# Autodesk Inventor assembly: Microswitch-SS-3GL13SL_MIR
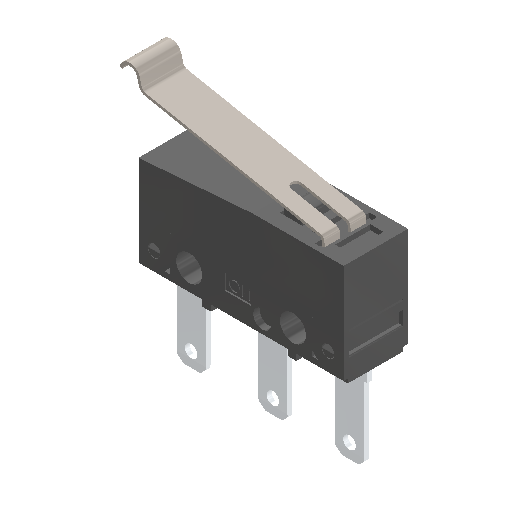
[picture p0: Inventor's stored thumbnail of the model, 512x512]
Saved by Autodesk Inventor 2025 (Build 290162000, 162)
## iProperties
Created: 2018-02
Part Number: Microswitch-SS-3GL13SL_MIR
Description: STEP AP214
Document SubType Name: Assembly
Designer: Ryzen5700u
Title: Microswitch-SS-3GL13SL.STEP
Revision Number: ANY
Sending System: SolidWorks 2018
Preprocessor: SwSTEP 2.0
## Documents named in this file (5)
- C:\Users\Ryzen5700u\Desktop\slider_2040\Microswitch-SS-3GL13SL\Microswitch-SS-3GL13SL_MIR.iam
- C:\Users\Ryzen5700u\Desktop\slider_2040\Microswitch-SS-3GL13SL\limit-switch-bottomcase_MIR.ipt
- C:\Users\Ryzen5700u\Desktop\slider_2040\Microswitch-SS-3GL13SL\limit-switch-top-case_MIR.ipt
- C:\Users\Ryzen5700u\Desktop\slider_2040\Microswitch-SS-3GL13SL\pins_MIR.ipt
- C:\Users\Ryzen5700u\Desktop\slider_2040\Microswitch-SS-3GL13SL\switch_lever_MIR.ipt
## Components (4 placed, 4 different names)
1. limit-switch-bottomcase_MIR:1
2. limit-switch-top-case_MIR:1
3. pins_MIR:1
4. switch_lever_MIR:1
